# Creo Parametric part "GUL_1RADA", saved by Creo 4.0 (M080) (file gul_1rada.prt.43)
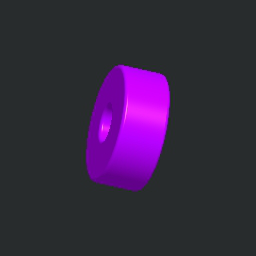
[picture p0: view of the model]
Units: Custom; MM, KILOGRAM, SECS
Materials in the file: OCEL_N

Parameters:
  MFG_WP_MATERIAL = "RO5_5"
  NAZOV = "GUL_1RADA"
  PTC_MATERIAL_NAME = "OCEL_N"

Other parameters: HMOTNOST, HUSTOTA

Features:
  1. round

Named dimensions: velke_D

Layers: 1, 2, 3, 4, 5, 6, 7, 8, 9, 10, 11, 12, 13, 14, 15, 16, 17, 18, 19, 20, 21, 22, 23, 24, 25, 26, 27, 28, 29, 30, 31, 32

Family table entries: GENERIC, LOZISKO_619, GUL_1RADA, value(d_val), 2/*, value(i_val), LOZISKO_623, GUL_1RADA, 2/$, LOZISKO_624, GUL_1RADA, 2/*, LOZISKO_634, GUL_1RADA, 2/0, LOZISKO_625, GUL_1RADA, 2/0, LOZISKO_635, GUL_1RADA, 2/3, LOZISKO_626, GUL_1RADA, 2/3, LOZISKO_607, GUL_1RADA, 2/3, LOZISKO_627, GUL_1RADA, 2/6, LOZISKO_608, GUL_1RADA, !/ , 2/6, LOZISKO_609, GUL_1RADA, !/", 2/8, LOZISKO_629, GUL_1RADA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

Surfaces: 8 torus, 2 plane, 2 cylinder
